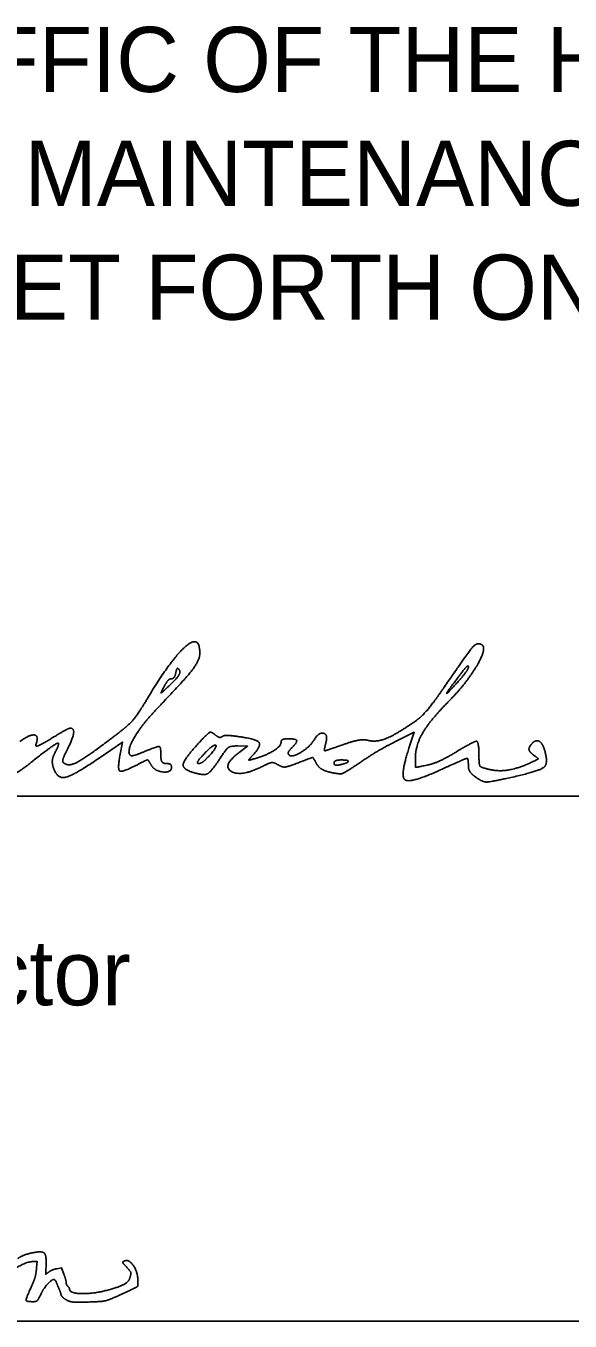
# Model space of a CAD drawing. Extents: x 0 to 34, y -7.5 to 22.
# Drawn here: x 26.511 to 27.681, y 7.234 to 10.02 of the extents above; entities that cross this region are included whole.
import ezdxf

# ---------------------------------------------------------------- set-up
doc = ezdxf.new("R2010")
doc.units = 0
for name, color, linetype in [('Default', 7, 'Continuous'), ('SH_Data', 7, 'Continuous'), ('SH_Text', 7, 'Continuous')]:
    doc.layers.add(name, color=color, linetype=linetype)

msp = doc.modelspace()

# ---------------------------------------------------------------- linework, layer by layer
at = {"layer": 'Default'}
for points in [[(26.534, 7.348), (26.5355, 7.3618), (26.5277, 7.3618)], [(26.5779, 7.3464), (26.5876, 7.3479), (26.5926, 7.3344)]]:
    msp.add_lwpolyline(points, dxfattribs=at)
for points in [[(26.5277, 7.3618), (26.515, 7.3618), (26.4812, 7.3434), (26.4691, 7.3298)], [(26.4938, 7.3684), (26.501, 7.3735), (26.5192, 7.3798), (26.5329, 7.3819)], [(26.5329, 7.3819), (26.5476, 7.3842), (26.5552, 7.3738), (26.5544, 7.3526)], [(26.7245, 7.3532), (26.7192, 7.3589), (26.719, 7.3615), (26.7236, 7.3633)], [(26.7236, 7.3633), (26.7322, 7.3666), (26.7506, 7.3417), (26.7516, 7.3254)], [(26.5194, 7.3002), (26.5284, 7.3201), (26.5324, 7.3332), (26.534, 7.348)], [(26.5544, 7.3526), (26.5537, 7.3342), (26.5536, 7.3345), (26.5613, 7.34)], [(26.5613, 7.34), (26.5651, 7.3427), (26.5726, 7.3455), (26.5779, 7.3464)], [(26.5926, 7.3344), (26.5954, 7.3269), (26.5977, 7.3188), (26.5977, 7.3163)], [(26.7336, 7.3241), (26.7376, 7.3359), (26.736, 7.3408), (26.7245, 7.3532)], [(26.5709, 7.3234), (26.5666, 7.3234), (26.5483, 7.3029), (26.5436, 7.2927)], [(26.5765, 7.3168), (26.575, 7.3204), (26.5725, 7.3234), (26.5709, 7.3234)], [(26.5824, 7.3027), (26.5806, 7.3068), (26.578, 7.3132), (26.5765, 7.3168)], [(26.5858, 7.2931), (26.5857, 7.2942), (26.5842, 7.2985), (26.5824, 7.3027)], [(26.5977, 7.3163), (26.5977, 7.3138), (26.5993, 7.3101), (26.6013, 7.3082)], [(26.6013, 7.3082), (26.6033, 7.3062), (26.6049, 7.3035), (26.6049, 7.3022)], [(26.6049, 7.3022), (26.6049, 7.2936), (26.6555, 7.2921), (26.6847, 7.2998)], [(26.6847, 7.2998), (26.7084, 7.306), (26.7314, 7.3174), (26.7336, 7.3241)], [(26.7516, 7.3254), (26.7526, 7.3101), (26.7499, 7.3069), (26.7265, 7.296)], [(26.5267, 7.2754), (26.5122, 7.2754), (26.5106, 7.2808), (26.5194, 7.3002)], [(26.5436, 7.2927), (26.5379, 7.2803), (26.5331, 7.2754), (26.5267, 7.2754)], [(26.6014, 7.2775), (26.5944, 7.2808), (26.5859, 7.2892), (26.5858, 7.2931)], [(26.6313, 7.2744), (26.6164, 7.2743), (26.6061, 7.2753), (26.6014, 7.2775)], [(26.7265, 7.296), (26.6917, 7.2796), (26.6707, 7.2749), (26.6313, 7.2744)]]:
    msp.add_open_spline(points, degree=2, dxfattribs=at)
at = {"layer": 'SH_Data'}
for p, q in [((24.5, 8.3631), (28, 8.3631)), ((24.5, 7.2337), (28, 7.2337))]:
    msp.add_line(p, q, dxfattribs=at)
at = {"layer": 'SH_Text'}
msp.add_line((26.8411, 8.6341), (26.8411, 8.6341), dxfattribs=at)
for points in [[(27.3075, 8.4813), (27.3462, 8.5006), (27.3348, 8.4659)], [(26.6683, 8.4448), (26.7186, 8.4792), (26.7137, 8.4532)], [(26.9668, 8.471), (26.9876, 8.4708), (26.9693, 8.4568)]]:
    msp.add_lwpolyline(points, dxfattribs=at)
for points in [[(26.885, 8.6701), (26.885, 8.7114), (26.8234, 8.6584), (26.7724, 8.5732)], [(26.7929, 8.551), (26.8522, 8.613), (26.885, 8.6554), (26.885, 8.6701)], [(27.4913, 8.6888), (27.4817, 8.6948), (27.4617, 8.6721), (27.4091, 8.5953)], [(27.4203, 8.567), (27.4591, 8.6063), (27.503, 8.6816), (27.4913, 8.6888)], [(26.8411, 8.6341), (26.8381, 8.6389), (26.8349, 8.6368), (26.8334, 8.6289)], [(27.4626, 8.641), (27.4626, 8.6371), (27.452, 8.6222), (27.439, 8.6077)], [(27.4461, 8.6261), (27.4552, 8.6382), (27.4626, 8.6449), (27.4626, 8.641)], [(26.8239, 8.6156), (26.8202, 8.6156), (26.8131, 8.6079), (26.8081, 8.5986)], [(26.8225, 8.6038), (26.8355, 8.6161), (26.8439, 8.6297), (26.8411, 8.6341)], [(26.8334, 8.6289), (26.8319, 8.6216), (26.8277, 8.6156), (26.8239, 8.6156)], [(27.439, 8.6077), (27.4144, 8.5804), (27.4175, 8.5882), (27.4461, 8.6261)], [(26.8081, 8.5986), (26.8005, 8.5844), (26.803, 8.5853), (26.8225, 8.6038)], [(27.4091, 8.5953), (27.3887, 8.5654), (27.3624, 8.5342), (27.3508, 8.526)], [(26.7724, 8.5732), (26.7499, 8.5357), (26.7281, 8.5121), (26.6877, 8.4817)], [(27.3486, 8.4452), (27.3486, 8.4722), (27.3812, 8.5274), (27.4203, 8.567)], [(26.7356, 8.4509), (26.7271, 8.4593), (26.7598, 8.5164), (26.7929, 8.551)], [(26.6066, 8.5092), (26.6039, 8.5092), (26.5852, 8.499), (26.5651, 8.4867)], [(26.5995, 8.4625), (26.6117, 8.4862), (26.6152, 8.5092), (26.6066, 8.5092)], [(26.9177, 8.4952), (26.9095, 8.5021), (26.9017, 8.4979), (26.8809, 8.4752)], [(27.1564, 8.4788), (27.161, 8.4964), (27.1404, 8.5004), (27.1305, 8.4838)], [(27.3508, 8.526), (27.3099, 8.4973), (27.2652, 8.4784), (27.2479, 8.4828)], [(26.5325, 8.4745), (26.5395, 8.4928), (26.5194, 8.4962), (26.4981, 8.4804)], [(26.5287, 8.4408), (26.5714, 8.4745), (26.5859, 8.4793), (26.5733, 8.4557)], [(26.5651, 8.4867), (26.545, 8.4743), (26.5303, 8.4688), (26.5325, 8.4745)], [(26.6877, 8.4817), (26.6367, 8.4434), (26.6008, 8.4261), (26.5915, 8.4353)], [(26.8809, 8.4752), (26.8513, 8.4428), (26.8474, 8.4213), (26.8698, 8.4142)], [(26.8926, 8.4521), (26.9135, 8.4744), (26.9244, 8.4709), (26.9041, 8.4484)], [(26.9329, 8.4911), (26.9303, 8.4886), (26.9235, 8.4904), (26.9177, 8.4952)], [(26.9288, 8.4446), (26.9416, 8.4644), (26.9512, 8.4711), (26.9668, 8.471)], [(26.9721, 8.4906), (26.9531, 8.4935), (26.9354, 8.4937), (26.9329, 8.4911)], [(26.9971, 8.449), (27.0173, 8.4702), (27.0083, 8.4852), (26.9721, 8.4906)], [(27.0598, 8.4796), (27.0598, 8.471), (27.0311, 8.4522), (27.0066, 8.4448)], [(27.075, 8.4864), (27.0667, 8.4864), (27.0598, 8.4833), (27.0598, 8.4796)], [(27.0812, 8.4652), (27.0945, 8.4785), (27.0922, 8.4864), (27.075, 8.4864)], [(27.1305, 8.4838), (27.1217, 8.469), (27.083, 8.4454), (27.0772, 8.4513)], [(27.1976, 8.4753), (27.1548, 8.4602), (27.1517, 8.4605), (27.1564, 8.4788)], [(27.2479, 8.4828), (27.2385, 8.4851), (27.2159, 8.4818), (27.1976, 8.4753)], [(27.2297, 8.4354), (27.2512, 8.4501), (27.2862, 8.4707), (27.3075, 8.4813)], [(27.4854, 8.4481), (27.4854, 8.4802), (27.4756, 8.4819), (27.4346, 8.457)], [(27.6257, 8.4646), (27.6207, 8.4804), (27.6032, 8.4835), (27.5949, 8.47)], [(26.5733, 8.4557), (26.5687, 8.4472), (26.5671, 8.4335), (26.5697, 8.4253)], [(26.5697, 8.4253), (26.5778, 8.3999), (26.6129, 8.4068), (26.6683, 8.4448)], [(26.5915, 8.4353), (26.5893, 8.4376), (26.5929, 8.4498), (26.5995, 8.4625)], [(26.7137, 8.4532), (26.7076, 8.4205), (26.7179, 8.4137), (26.7492, 8.4298)], [(26.7658, 8.4587), (26.7511, 8.4525), (26.7374, 8.449), (26.7356, 8.4509)], [(26.8014, 8.4471), (26.8014, 8.4686), (26.7948, 8.4708), (26.7658, 8.4587)], [(26.8128, 8.4332), (26.8066, 8.4332), (26.8014, 8.4394), (26.8014, 8.4471)], [(26.8698, 8.4142), (26.8931, 8.4068), (26.91, 8.4155), (26.9288, 8.4446)], [(26.8825, 8.4332), (26.8783, 8.4332), (26.8828, 8.4417), (26.8926, 8.4521)], [(26.9041, 8.4484), (26.8965, 8.44), (26.8868, 8.4332), (26.8825, 8.4332)], [(26.9693, 8.4568), (26.9316, 8.4278), (26.9753, 8.4039), (27.0218, 8.4281)], [(27.0066, 8.4448), (26.9911, 8.4401), (26.9894, 8.4409), (26.9971, 8.449)], [(27.0772, 8.4513), (27.0745, 8.454), (27.0763, 8.4603), (27.0812, 8.4652)], [(27.0972, 8.435), (27.1266, 8.4465), (27.1287, 8.4464), (27.1358, 8.4332)], [(27.3348, 8.4659), (27.3148, 8.4051), (27.3387, 8.3902), (27.4066, 8.4212)], [(27.3733, 8.4296), (27.3502, 8.4247), (27.3486, 8.4257), (27.3486, 8.4452)], [(27.4346, 8.457), (27.4145, 8.4448), (27.3869, 8.4324), (27.3733, 8.4296)], [(27.4066, 8.4212), (27.4567, 8.4442), (27.4626, 8.4449), (27.4626, 8.4283)], [(27.5045, 8.4211), (27.4896, 8.4248), (27.4854, 8.4307), (27.4854, 8.4481)], [(27.5538, 8.4031), (27.6153, 8.4167), (27.6354, 8.4339), (27.6257, 8.4646)], [(27.5949, 8.47), (27.5919, 8.4652), (27.5951, 8.4572), (27.6019, 8.4522)], [(27.6019, 8.4522), (27.6131, 8.444), (27.6125, 8.4422), (27.5962, 8.4348)], [(26.4825, 8.4104), (26.4868, 8.4104), (26.5076, 8.424), (26.5287, 8.4408)], [(26.7492, 8.4298), (26.7713, 8.4413), (26.7739, 8.4413), (26.7802, 8.4302)], [(26.7802, 8.4302), (26.7876, 8.4169), (26.8242, 8.4131), (26.8242, 8.4256)], [(26.8242, 8.4256), (26.8242, 8.4297), (26.8191, 8.4332), (26.8128, 8.4332)], [(27.0218, 8.4281), (27.035, 8.4349), (27.0447, 8.4356), (27.0535, 8.4303)], [(27.0535, 8.4303), (27.0624, 8.425), (27.0752, 8.4263), (27.0972, 8.435)], [(27.1358, 8.4332), (27.1399, 8.4255), (27.1539, 8.4169), (27.1669, 8.414)], [(27.1669, 8.414), (27.1862, 8.4098), (27.1975, 8.4136), (27.2297, 8.4354)], [(27.1738, 8.4339), (27.1738, 8.4377), (27.1807, 8.4408), (27.189, 8.4408)], [(27.189, 8.431), (27.1807, 8.4288), (27.1738, 8.4301), (27.1738, 8.4339)], [(27.189, 8.4408), (27.1974, 8.4408), (27.2042, 8.4395), (27.2042, 8.4379)], [(27.2042, 8.4379), (27.2042, 8.4363), (27.1974, 8.4332), (27.189, 8.431)], [(27.4626, 8.4283), (27.4626, 8.4215), (27.4686, 8.4113), (27.4759, 8.4057)], [(27.5962, 8.4348), (27.5684, 8.4221), (27.5257, 8.4158), (27.5045, 8.4211)], [(27.4759, 8.4057), (27.4919, 8.3936), (27.5085, 8.3931), (27.5538, 8.4031)]]:
    msp.add_open_spline(points, degree=2, dxfattribs=at)

# ---------------------------------------------------------------- texts
for s, p in [('THE CLOSING TO TRAFFIC OF THE HIGHWAY AND THAT ', (24.4169, 9.8779)), ('PROVISIONS FOR THE MAINTENANCE AND SAFETY OF', (24.4169, 9.6329)), ('TRAFFIC WILL BE AS SET FORTH ON THE PLANS AND', (24.4169, 9.3879)), ('District       Deputy Director', (24.5, 7.9131))]:
    msp.add_text(s, height=0.14, dxfattribs=at).set_placement(p)

doc.saveas('drawing.dxf')
